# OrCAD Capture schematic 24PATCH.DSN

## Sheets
1 24Patch: size A4; title: 24Patch; rev: 0.1; note: 24Patch
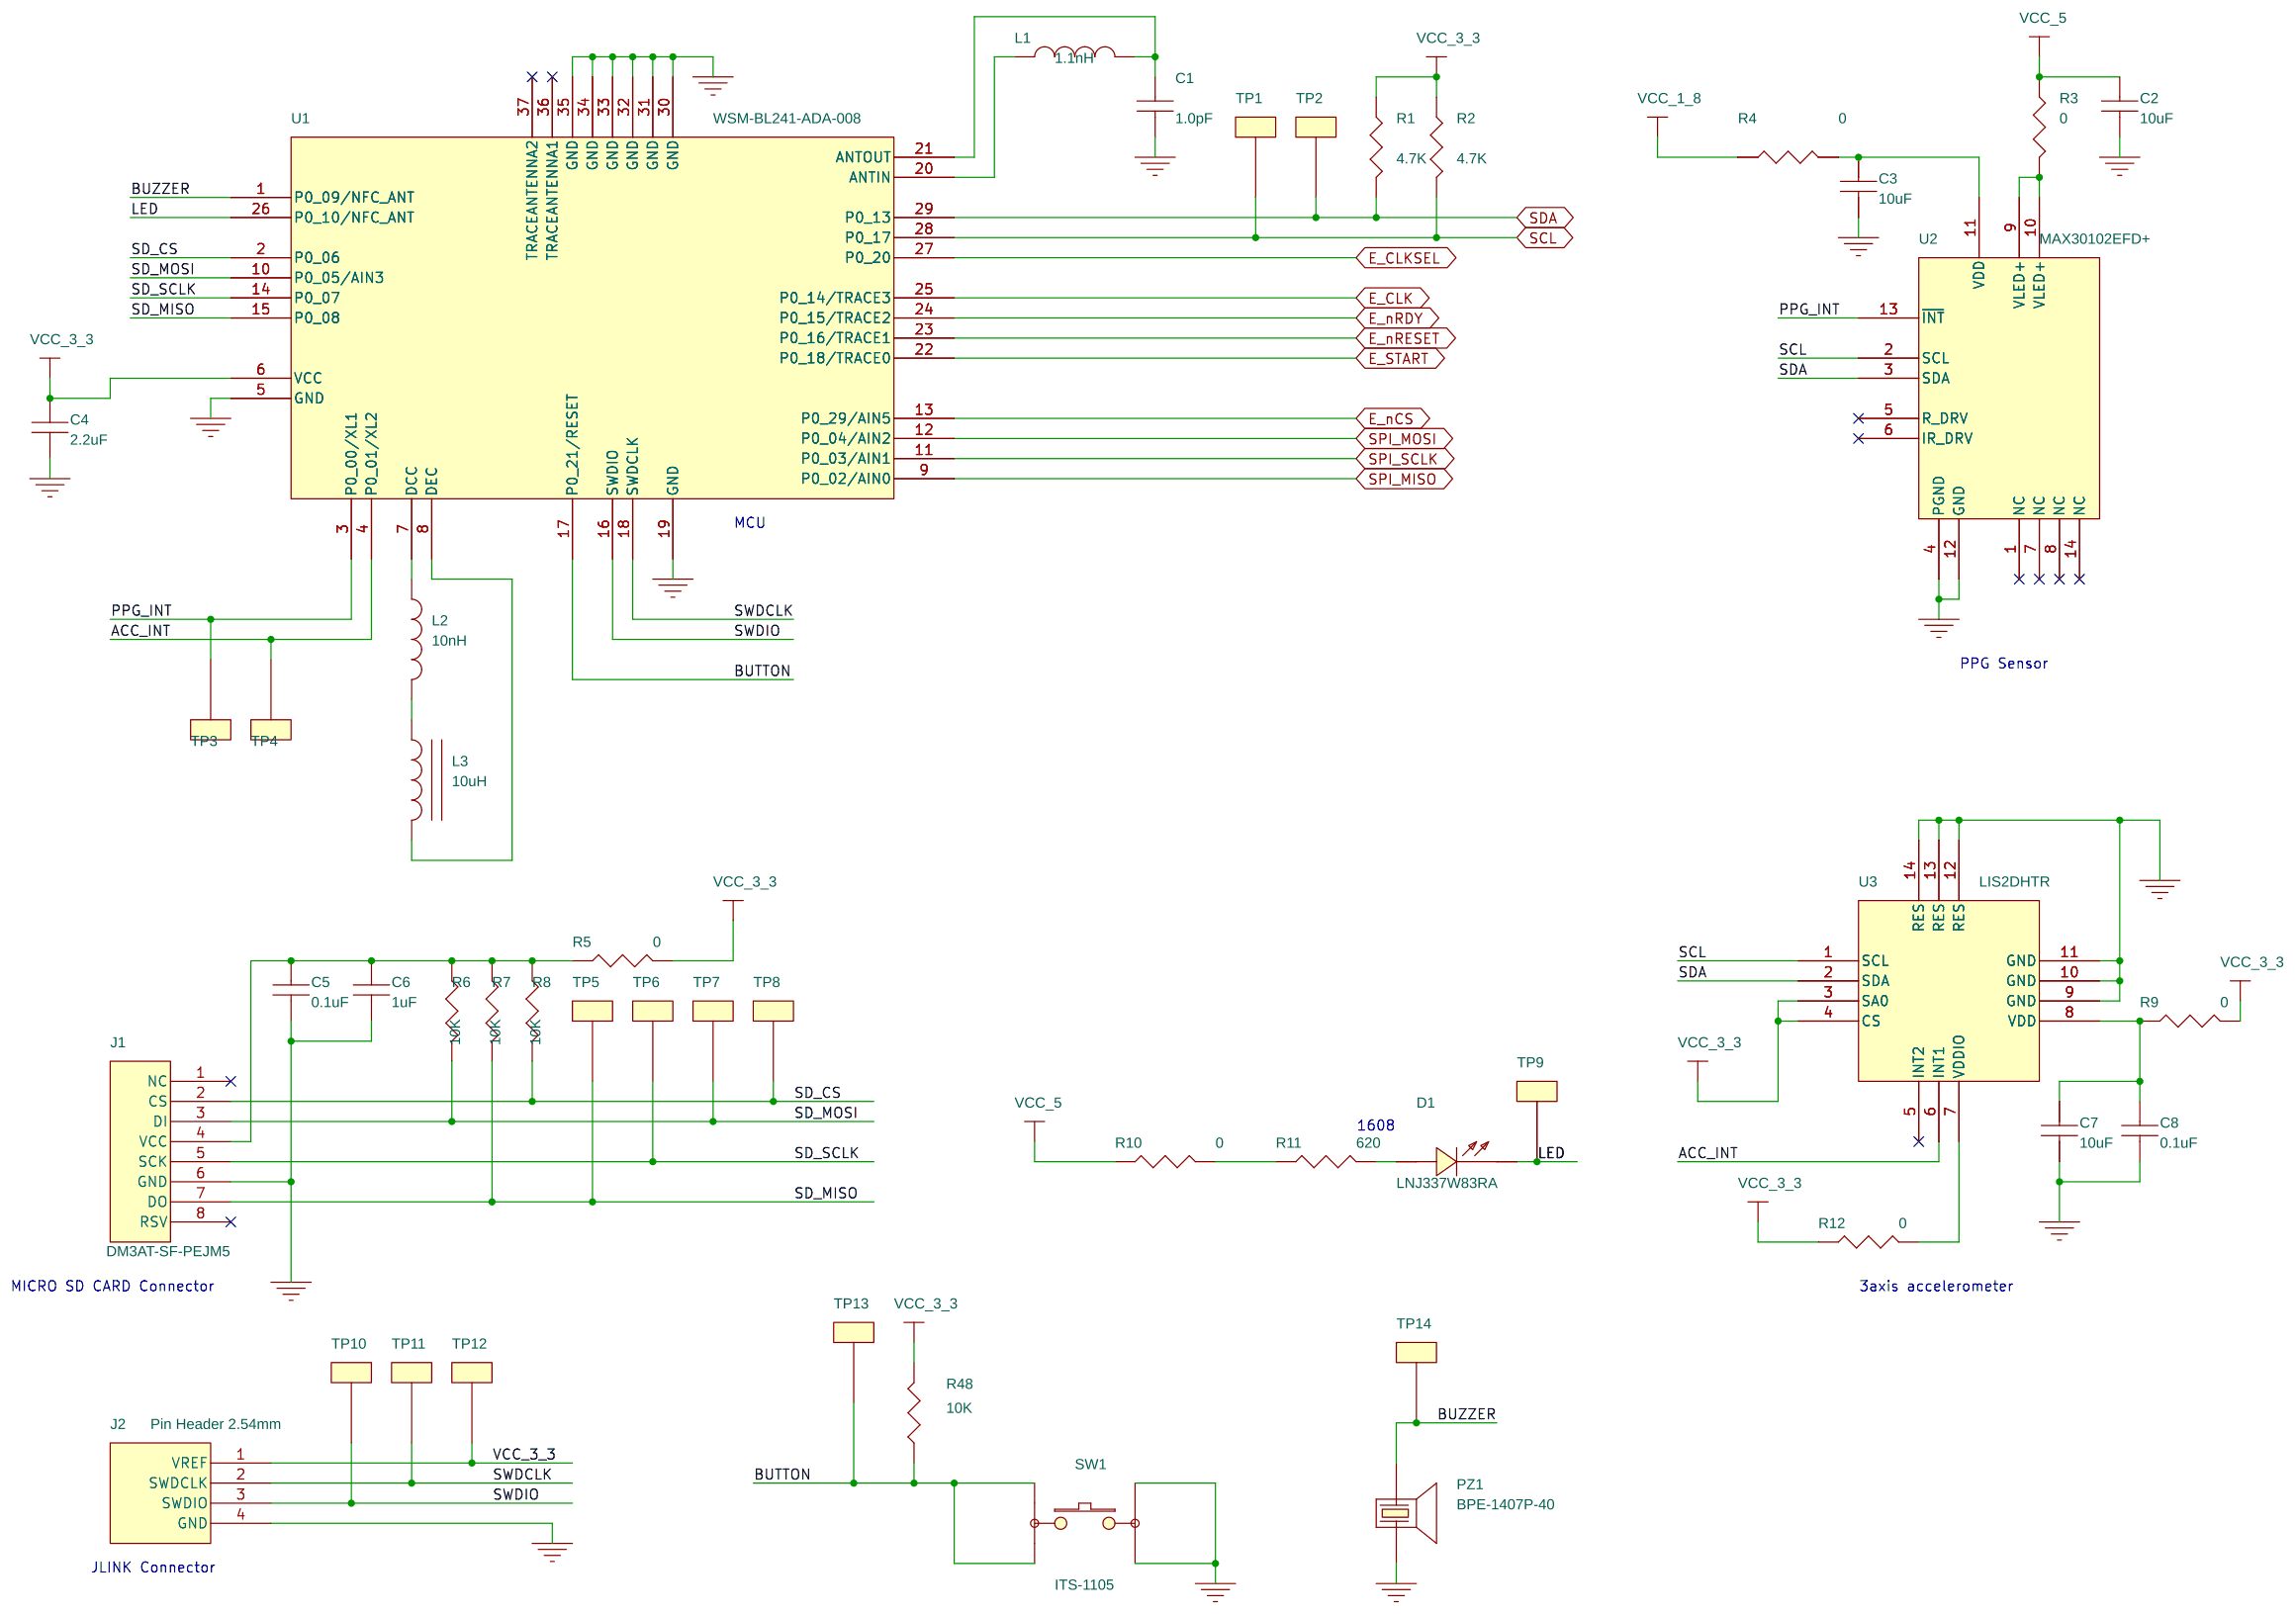
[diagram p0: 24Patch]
2 24Patch_ECG: size A4; title: 24Patch_ECG
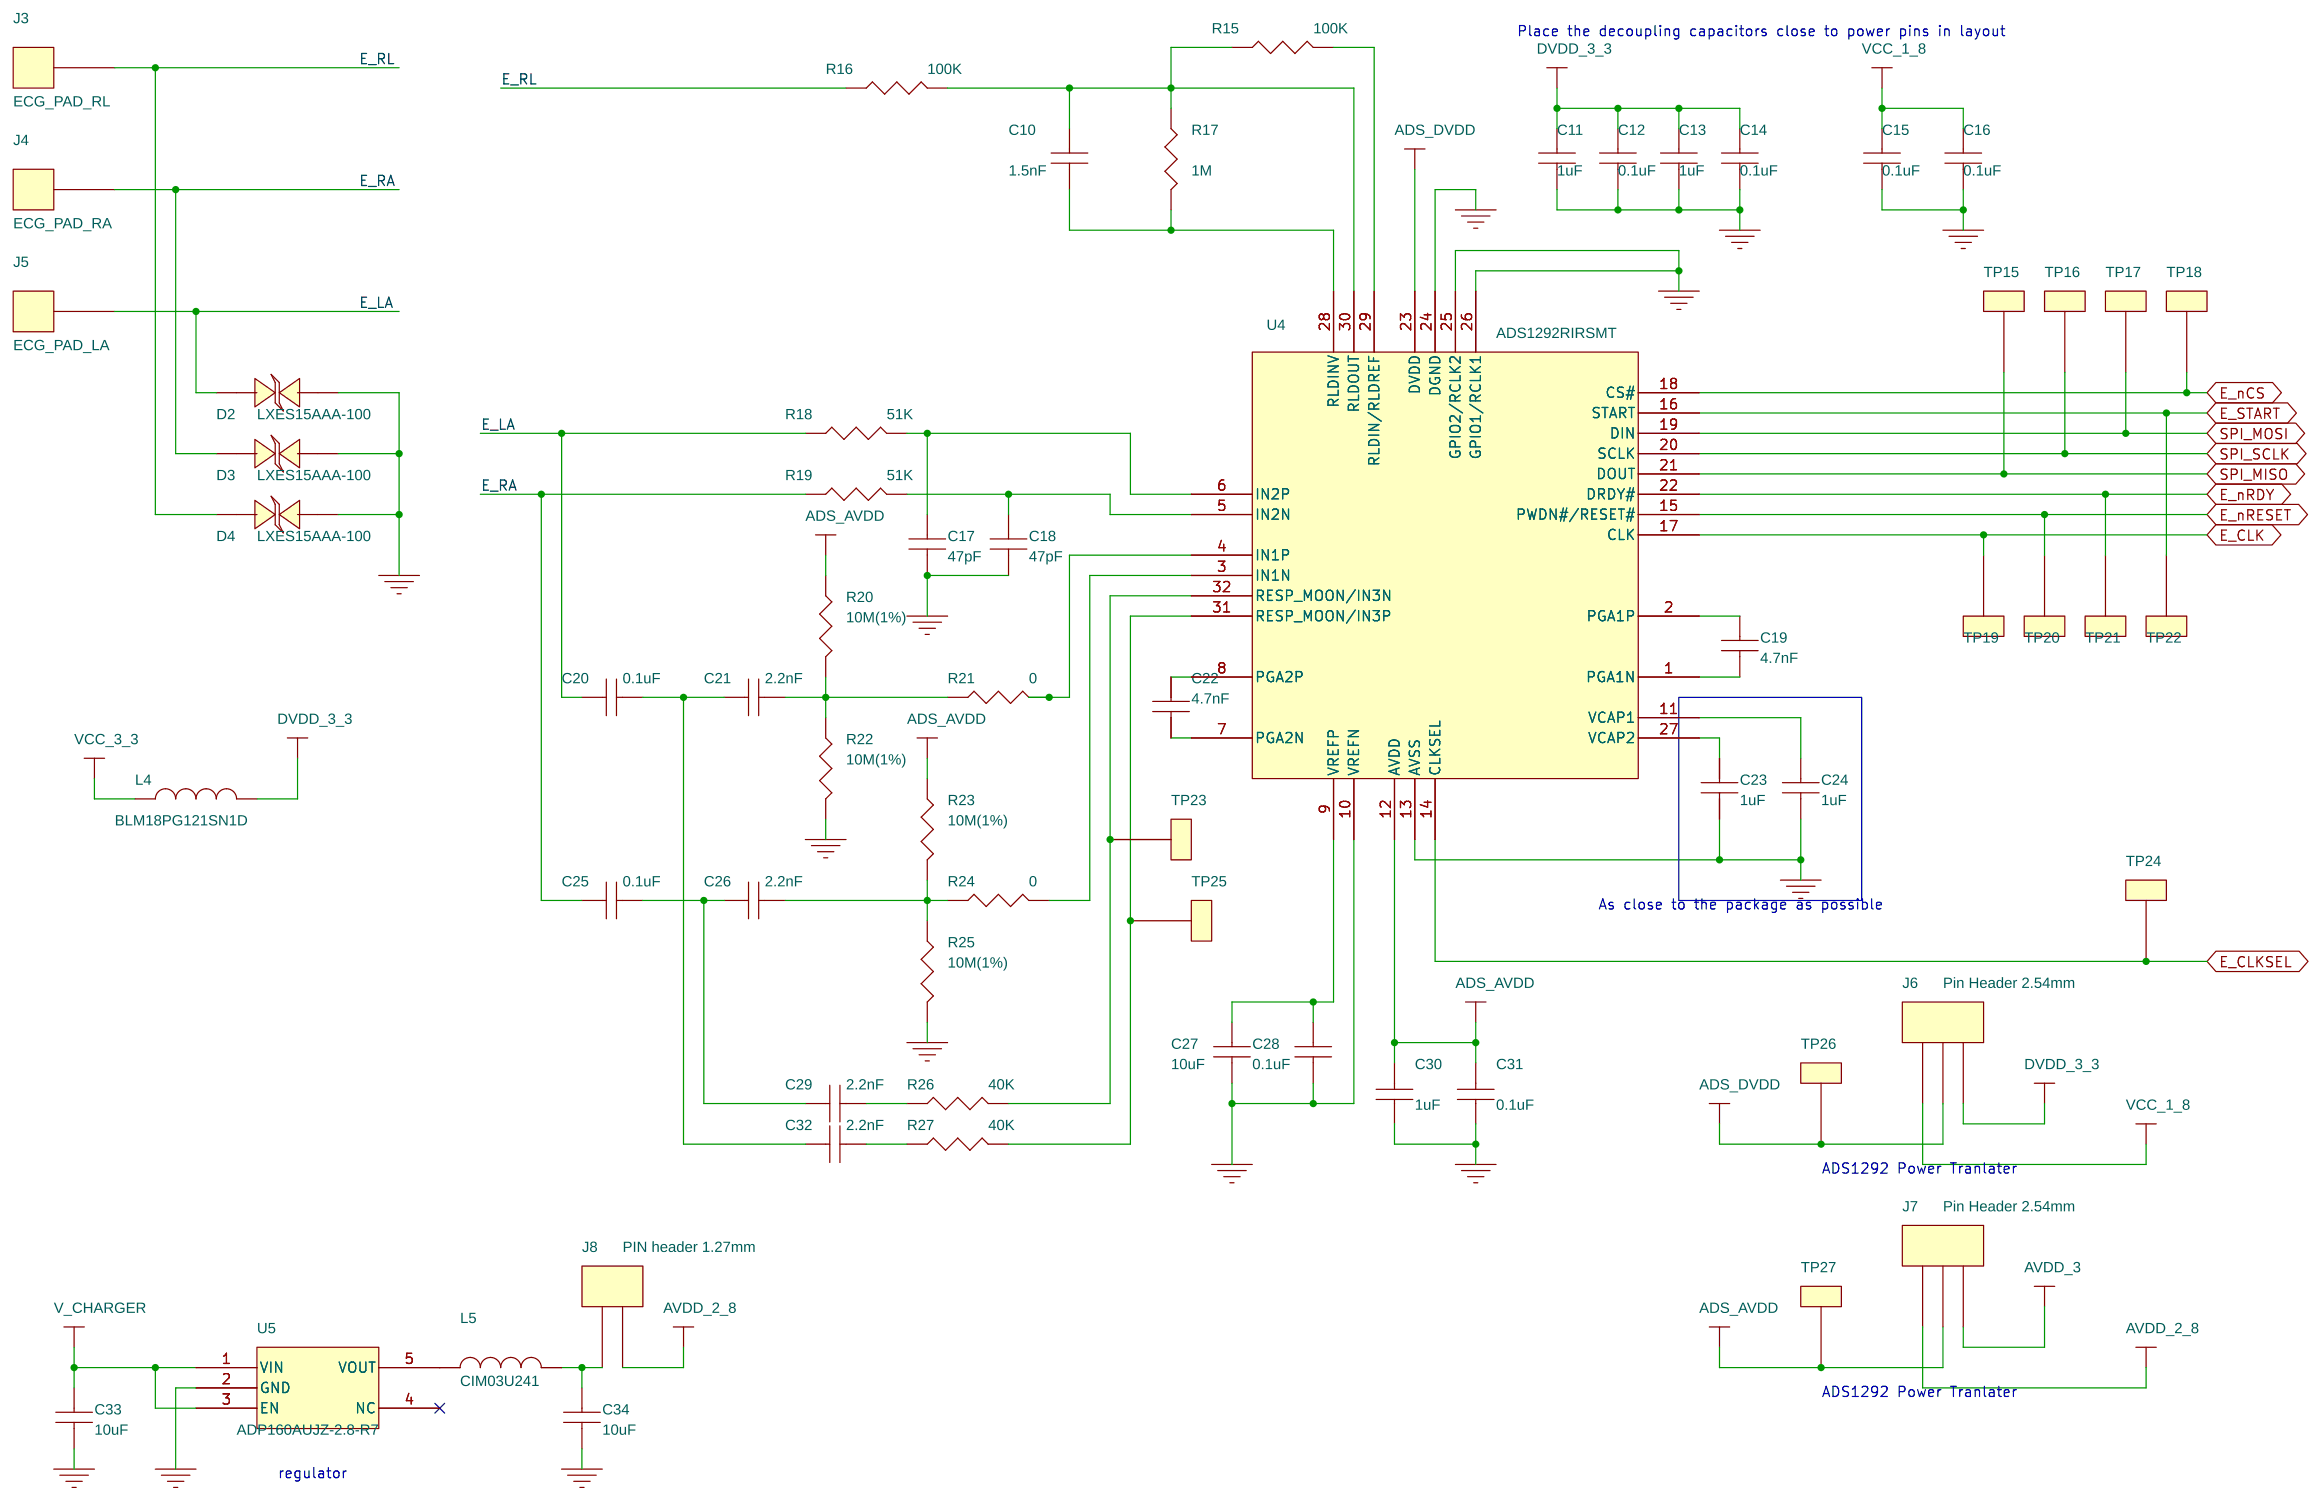
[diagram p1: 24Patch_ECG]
3 24Patch_Power: size A4; title: 24Patch Power Supply
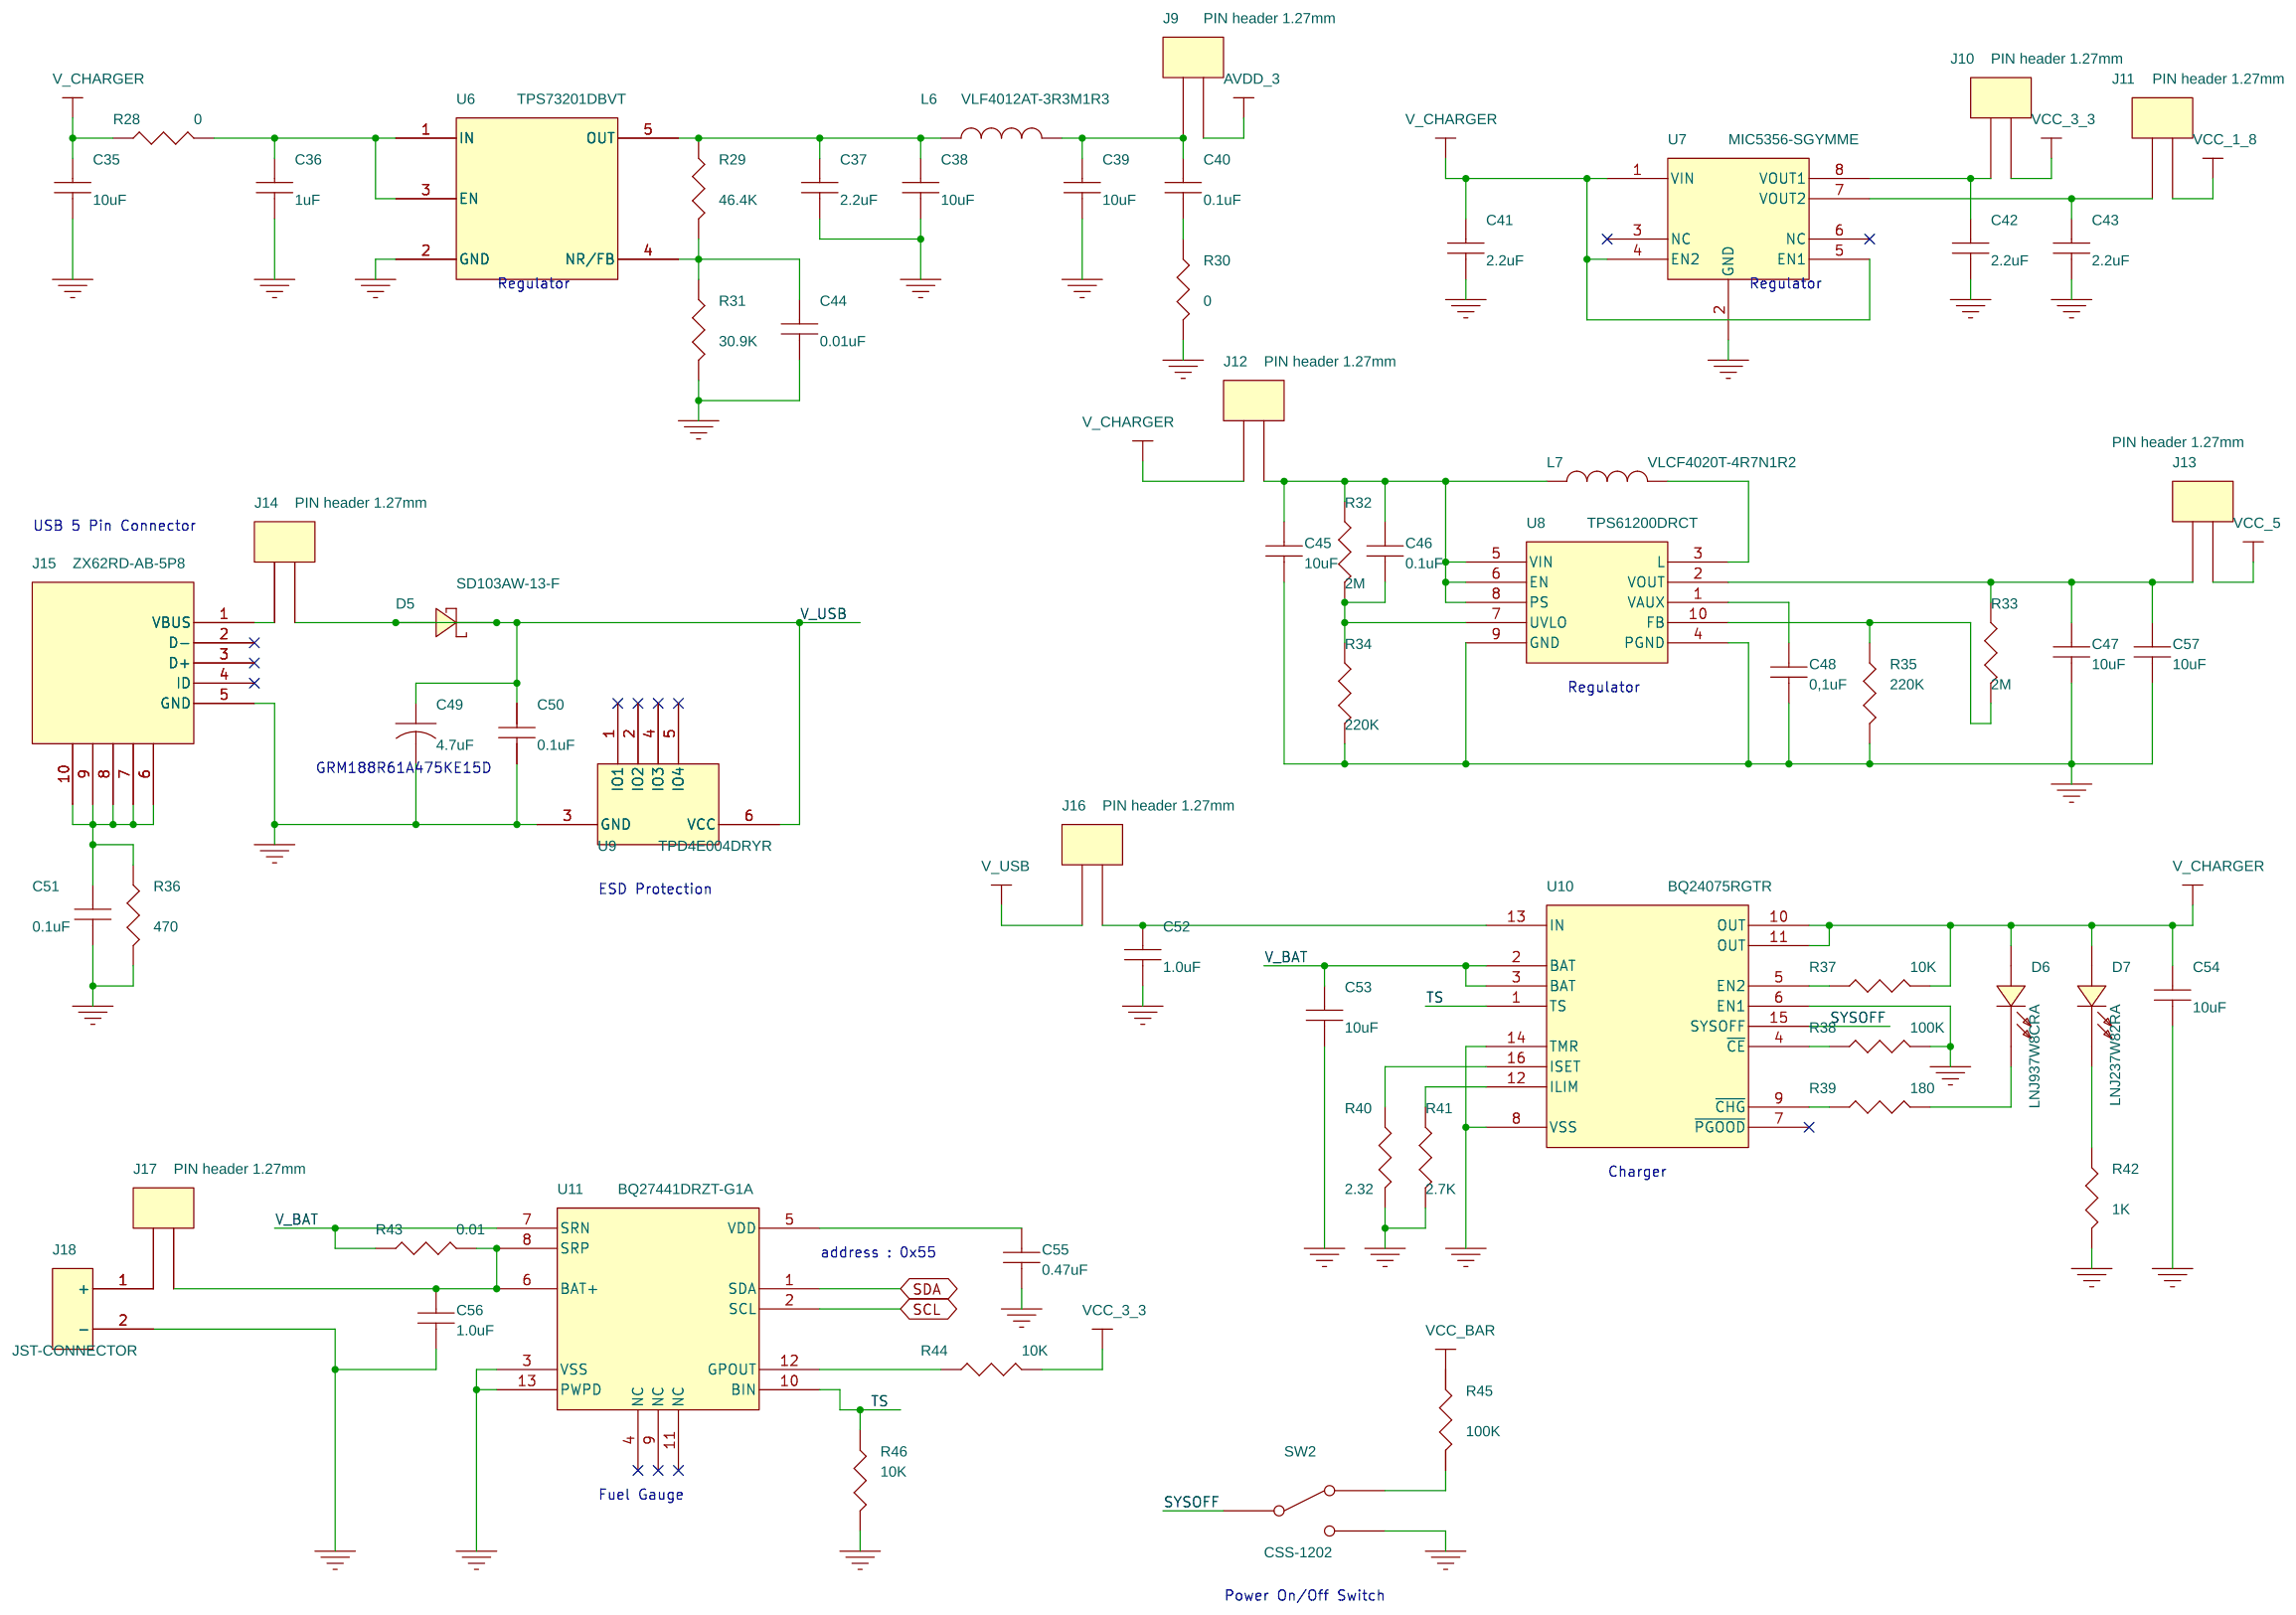
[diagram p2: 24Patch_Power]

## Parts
sheet 24Patch
C1  1.0pF
C2  10uF
C3  10uF
C4  2.2uF
C5  0.1uF
C6  1uF
C7  10uF
C8  0.1uF
D1  LNJ337W83RA
J1  DM3AT-SF-PEJM5
J2  Pin Header 2.54mm
L1  1.1nH
L2  10nH
L3  10uH
PZ1  BPE-1407P-40
R1  4.7K
R2  4.7K
R3  0
R4  0
R5  0
R6  10K
R7  10K
R8  10K
R9  0
R10  0
R11  620
R12  0
R48  10K
SW1  ITS-1105
TP1  TEST POINT
TP2  TEST POINT
TP3  TEST POINT
TP4  TEST POINT
TP5  TEST POINT
TP6  TEST POINT
TP7  TEST POINT
TP8  TEST POINT
TP9  TEST POINT
TP10  TEST POINT
TP11  TEST POINT
TP12  TEST POINT
TP13  TEST POINT
TP14  TEST POINT
U1  WSM-BL241-ADA-008
U2  MAX30102EFD+
U3  LIS2DHTR
sheet 24Patch_ECG
C10  1.5nF
C11  1uF
C12  0.1uF
C13  1uF
C14  0.1uF
C15  0.1uF
C16  0.1uF
C17  47pF
C18  47pF
C19  4.7nF
C20  0.1uF
C21  2.2nF
C22  4.7nF
C23  1uF
C24  1uF
C25  0.1uF
C26  2.2nF
C27  10uF
C28  0.1uF
C29  2.2nF
C30  1uF
C31  0.1uF
C32  2.2nF
C33  10uF
C34  10uF
D2  LXES15AAA-100
D3  LXES15AAA-100
D4  LXES15AAA-100
J3  ECG_PAD_RL
J4  ECG_PAD_RA
J5  ECG_PAD_LA
J6  Pin Header 2.54mm
J7  Pin Header 2.54mm
J8  PIN header 1.27mm
L4  BLM18PG121SN1D
L5  CIM03U241
R15  100K
R16  100K
R17  1M
R18  51K
R19  51K
R20  10M(1%)
R21  0
R22  10M(1%)
R23  10M(1%)
R24  0
R25  10M(1%)
R26  40K
R27  40K
TP15  TEST POINT
TP16  TEST POINT
TP17  TEST POINT
TP18  TEST POINT
TP19  TEST POINT
TP20  TEST POINT
TP21  TEST POINT
TP22  TEST POINT
TP23  TEST POINT
TP24  TEST POINT
TP25  TEST POINT
TP26  TEST POINT
TP27  TEST POINT
U4  ADS1292RIRSMT
U5  ADP160AUJZ-2.8-R7
sheet 24Patch_Power
C35  10uF
C36  1uF
C37  2.2uF
C38  10uF
C39  10uF
C40  0.1uF
C41  2.2uF
C42  2.2uF
C43  2.2uF
C44  0.01uF
C45  10uF
C46  0.1uF
C47  10uF
C48  0,1uF
C49  4.7uF
C50  0.1uF
C51  0.1uF
C52  1.0uF
C53  10uF
C54  10uF
C55  0.47uF
C56  1.0uF
C57  10uF
D5  SD103AW-13-F
D6  LNJ937W8CRA
D7  LNJ237W82RA
J9  PIN header 1.27mm
J10  PIN header 1.27mm
J11  PIN header 1.27mm
J12  PIN header 1.27mm
J13  PIN header 1.27mm
J14  PIN header 1.27mm
J15  ZX62RD-AB-5P8
J16  PIN header 1.27mm
J17  PIN header 1.27mm
J18  JST-CONNECTOR
L6  VLF4012AT-3R3M1R3
L7  VLCF4020T-4R7N1R2
R28  0
R29  46.4K
R30  0
R31  30.9K
R32  2M
R33  2M
R34  220K
R35  220K
R36  470
R37  10K
R38  100K
R39  180
R40  2.32
R41  2.7K
R42  1K
R43  0.01
R44  10K
R45  100K
R46  10K
SW2  CSS-1202
U6  TPS73201DBVT
U7  MIC5356-SGYMME
U8  TPS61200DRCT
U9  TPD4E004DRYR
U10  BQ24075RGTR
U11  BQ27441DRZT-G1A

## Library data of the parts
C1-C8 C10-C48 C50-C57 = CAP_NP
D1 D6 D7 = LED
J1 = DM3AT-SF-PEJM5
J2 = JLINK_CONNECTOR
L1 L2 L4-L7 = INDUCTOR
L3 = INDUCTOR_IRON
PZ1 = PIEZO_BUZZER_2
R1-R12 R15-R46 R48 = R
SW1 = SW_PUSHBUTTON-SPST-2
TP1-TP27 = TEST_POINT
U1 = WSM-BL241-ADA-008
U2 = MAX30102EFD+
U3 = LIS2DHTR
D2-D4 = DIODE_TVS_BI-DIR
J3-J5 = CON1
J6 J7 = CON3
J8-J14 J16 J17 = CON2
U4 = ADS1292RIRSMT
U5 = ADP160AUJZ-2.8-R7
C49 = CAP
D5 = DIODE_SCHOTTKY
J15 = ZX62RD-AB-5P8
J18 = JST-CONNECTOR
SW2 = SW_KEY-SPDT
U6 = TPS73201
U7 = MIC5356-SGYMME
U8 = TPS61200
U9 = TPD4E004DRYR
U10 = BQ24075
U11 = BQ27441-G1

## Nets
AVDD_2_8: J7.1 J8.2
AVDD_3: J7.3 J9.2
DVDD_3_3: C11.1 C12.1 C13.1 C14.1 J6.3 L4.2
GND: C1.2 C2.2 C3.2 C4.2 C5.2 C6.2 C7.2 C8.2 C11.2 C12.2 C13.2 C14.2 C15.2 C16.2 C17.2 C18.2 C23.2 C24.2 C27.2 C28.2 C30.1 C31.1 C33.2 C34.2 C35.2 C36.2 C37.2 C38.2 C39.2 C41.2 C42.2 C43.2 C44.2 C45.2 C47.2 C48.2 C49.2 C50.2 C51.2 C52.2 C53.2 C54.2 C55.2 C56.2 C57.2 D2.2 D3.2 D4.2 J1.6(GND) J2.4(GND) J15.5(GND) J18.2(-) PZ1.- R22.2 R25.2 R30.2 R31.2 R34.2 R35.2 R36.2 R38.2 R40.2 R41.2 R42.2 R46.2 SW1.3 SW1.4 SW2.3(NO) U1.5(GND) U1.19(GND) U1.30(GND) U1.31(GND) U1.32(GND) U1.33(GND) U1.34(GND) U1.35(GND) U2.4(PGND) U2.12(GND) U3.9(GND) U3.10(GND) U3.11(GND) U3.12(RES) U3.13(RES) U3.14(RES) U4.10(VREFN) U4.13(AVSS) U4.24(DGND) U4.25(GPIO2/RCLK2) U4.26(GPIO1/RCLK1) U5.2(GND) U6.2(GND) U7.2(GND) U8.4(PGND) U8.9(GND) U9.3(GND) U10.6(EN1) U10.8(VSS) U10.14(TMR) U11.3(VSS) U11.13(PWPD)
VCC_1_8: C15.1 C16.1 J6.1 J11.2 R4.1
VCC_3_3: C4.1 J2.1(VREF) J10.2 L4.1 R1.1 R2.1 R5.2 R9.2 R12.1 R44.2 R48.2 TP12.1 U1.6(VCC) U3.3(SA0) U3.4(CS)
VCC_5: C2.1 J13.2 R3.1 R10.1
ACC_INT: TP4.1 U1.4(P0_01/XL2) U3.6(INT1)
ADS_AVDD: C30.2 C31.2 J7.2 R20.1 R23.1 TP27.1 U4.12(AVDD)
ADS_DVDD: J6.2 TP26.1 U4.23(DVDD)
BUTTON: R48.1 SW1.1 SW1.2 TP13.1 U1.17(P0_21/RESET)
BUZZER: PZ1.+ TP14.1 U1.1(P0_09/NFC_ANT)
E_CLK: TP19.1 U1.25(P0_14/TRACE3) U4.17(CLK)
E_CLKSEL: TP24.1 U1.27(P0_20) U4.14(CLKSEL)
E_LA: C20.1 D2.1 J5.1 R18.1
E_nCS: TP18.1 U1.13(P0_29/AIN5) U4.18(CS#)
E_nRDY: TP21.1 U1.24(P0_15/TRACE2) U4.22(DRDY#)
E_nRESET: TP20.1 U1.23(P0_16/TRACE1) U4.15(PWDN#/RESET#)
E_RA: C25.1 D3.1 J4.1 R19.1
E_RL: D4.1 J3.1 R16.1
E_START: TP22.1 U1.22(P0_18/TRACE0) U4.16(START)
LED: D1.1(CATHODE) TP9.1 U1.26(P0_10/NFC_ANT)
PPG_INT: TP3.1 U1.3(P0_00/XL1) U2.13(~{INT})
SCL: R2.2 TP1.1 U1.28(P0_17) U2.2(SCL) U3.1(SCL) U11.2(SCL)
SD_CS: J1.2(CS) R8.2 TP8.1 U1.2(P0_06)
SD_MISO: J1.7(DO) R7.2 TP5.1 U1.15(P0_08)
SD_MOSI: J1.3(DI) R6.2 TP7.1 U1.10(P0_05/AIN3)
SD_SCLK: J1.5(SCK) TP6.1 U1.14(P0_07)
SDA: R1.2 TP2.1 U1.29(P0_13) U2.3(SDA) U3.2(SDA) U11.1(SDA)
SPI_MISO: TP15.1 U1.9(P0_02/AIN0) U4.21(DOUT)
SPI_MOSI: TP17.1 U1.12(P0_04/AIN2) U4.19(DIN)
SPI_SCLK: TP16.1 U1.11(P0_03/AIN1) U4.20(SCLK)
SWDCLK: J2.2(SWDCLK) TP11.1 U1.18(SWDCLK)
SWDIO: J2.3(SWDIO) TP10.1 U1.16(SWDIO)
SYSOFF: SW2.1(COMMON) U10.15(SYSOFF)
TS: R46.1 U10.1(TS) U11.10(BIN)
V_BAT: C53.1 R43.1 R45.1 U10.2(BAT) U10.3(BAT) U11.7(SRN)
V_CHARGER: C33.1 C35.1 C41.1 C54.1 D6.2(ANODE) D7.2(ANODE) J12.1 R28.1 R37.2 U5.1(VIN) U5.3(EN) U7.1(VIN) U7.4(EN2) U7.5(EN1) U10.10(OUT) U10.11(OUT)
V_USB: C49.1 C50.1 D5.1(ANODE) D5.2(CATHODE) J14.2 J16.1 U9.6(VCC)
N00732: C37.1 C38.1 L6.1 R29.1 U6.5(OUT)
N00736: C44.1 R29.2 R31.1 U6.4(NR/FB)
N00849: C39.1 C40.1 J9.1 L6.2
N01050: C36.1 R28.2 U6.1(IN) U6.3(EN)
N02515: C51.1 J15.6 J15.7 J15.8 J15.9 J15.10 R36.1
N11484: C56.1 J17.2 R43.2 U11.6(BAT+) U11.8(SRP)
N12401: C55.1 U11.5(VDD)
N12737: R44.1 U11.12(GPOUT)
N13916: C17.1 R18.2 U4.6(IN2P)
N14004: C18.1 R19.2 U4.5(IN2N)
N14266: R21.2 U4.4(IN1P)
N14441: C21.2 R20.2 R21.1 R22.1
N14716: C20.2 C21.1 C32.1
N14796: R24.2 U4.3(IN1N)
N14963: C26.2 R23.2 R24.1 R25.1
N15164: C25.2 C26.1 C29.1
N15196: R26.2 TP23.1 U4.32(RESP_MOON/IN3N)
N15211: R27.2 TP25.1 U4.31(RESP_MOON/IN3P)
N15507: C29.2 R26.1
N15511: C32.2 R27.1
N15587: C22.1 U4.8(PGA2P)
N15591: C22.2 U4.7(PGA2N)
N15668: C27.1 C28.1 U4.9(VREFP)
N16643: C23.1 U4.27(VCAP2)
N16652: C24.1 U4.11(VCAP1)
N16814: C19.1 U4.2(PGA1P)
N16818: C19.2 U4.1(PGA1N)
N17301: C10.2 R17.2 U4.28(RLDINV)
N17328: C10.1 R15.1 R16.2 R17.1 U4.30(RLDOUT)
N17358: R15.2 U4.29(RLDIN/RLDREF)
N22956: C3.1 R4.2 U2.11(VDD)
N22971: R3.2 U2.9(VLED+) U2.10(VLED+)
N23807: C7.1 C8.1 R9.1 U3.8(VDD)
N24014: R12.2 U3.7(VDDIO)
N25121: L2.2 L3.1
N25125: L2.1 U1.7(DCC)
N25129: L3.2 U1.8(DEC)
N25567: C5.1 C6.1 J1.4(VCC) R5.1 R6.1 R7.1 R8.1
N26966: D1.2(ANODE) R11.2
N31091: L1.1 U1.20(ANTIN)
N31106: C1.1 L1.2 U1.21(ANTOUT)
N38165: C52.1 J16.2 U10.13(IN)
N38879: R40.1 U10.16(ISET)
N38888: R41.1 U10.12(ILIM)
N39340: R37.1 U10.5(EN2)
N39557: R38.1 U10.4(~{CE})
N41222: D6.1(CATHODE) R39.2
N41343: R39.1 U10.9(~{CHG})
N41500: D7.1(CATHODE) R42.1
N43671: R45.2 SW2.8(NC)
N44529: C45.1 C46.1 J12.2 L7.1 R32.1 U8.5(VIN) U8.6(EN) U8.8(PS)
N44661: C48.1 U8.1(VAUX)
N45567: L7.2 U8.3(L)
N45883: R33.2 R35.1 U8.10(FB)
N46177: C47.1 C57.1 J13.1 R33.1 U8.2(VOUT)
N47383: C46.2 R32.2 R34.1 U8.7(UVLO)
N51655: C42.1 J10.1 U7.8(VOUT1)
N51666: C43.1 J11.1 U7.7(VOUT2)
N60244: J14.1 J15.1(VBUS)
N67347: C34.1 J8.1 L5.2
N79517: C40.2 R30.1
N85452: J17.1 J18.1(+)
N88679: L5.1 U5.5(VOUT)
N95954: R10.2 R11.1

Not connected (* = marked no-connect by the designer): J1 1(NC)* 8(RSV)*; J15 2(D-)* 3(D+)* 4(ID)*; U1 36(TRACEANTENNA1)* 37(TRACEANTENNA2)*; U2 1(NC)* 5(R_DRV)* 6(IR_DRV)* 7(NC)* 8(NC)* 14(NC)*; U3 5(INT2)*; U5 4(NC)*; U7 3(NC)* 6(NC)*; U9 1(IO1)* 2(IO2)* 4(IO3)* 5(IO4)*; U10 7(~{PGOOD})*; U11 4(NC)* 9(NC)* 11(NC)*

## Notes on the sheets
sheet 1
- MCU
- PPG Sensor
- 1608
- MICRO SD CARD Connector
- 3axis accelerometer
- JLINK Connector
sheet 2
- Place the decoupling capacitors close to power pins in layout
- As close to the package as possible
- ADS1292 Power Tranlater
- ADS1292 Power Tranlater
- regulator
sheet 3
- Regulator
- Regulator
- USB 5 Pin Connector
- Regulator
- GRM188R61A475KE15D
- ESD Protection
- Charger
- address : 0x55
- Fuel Gauge
- Power On/Off Switch
